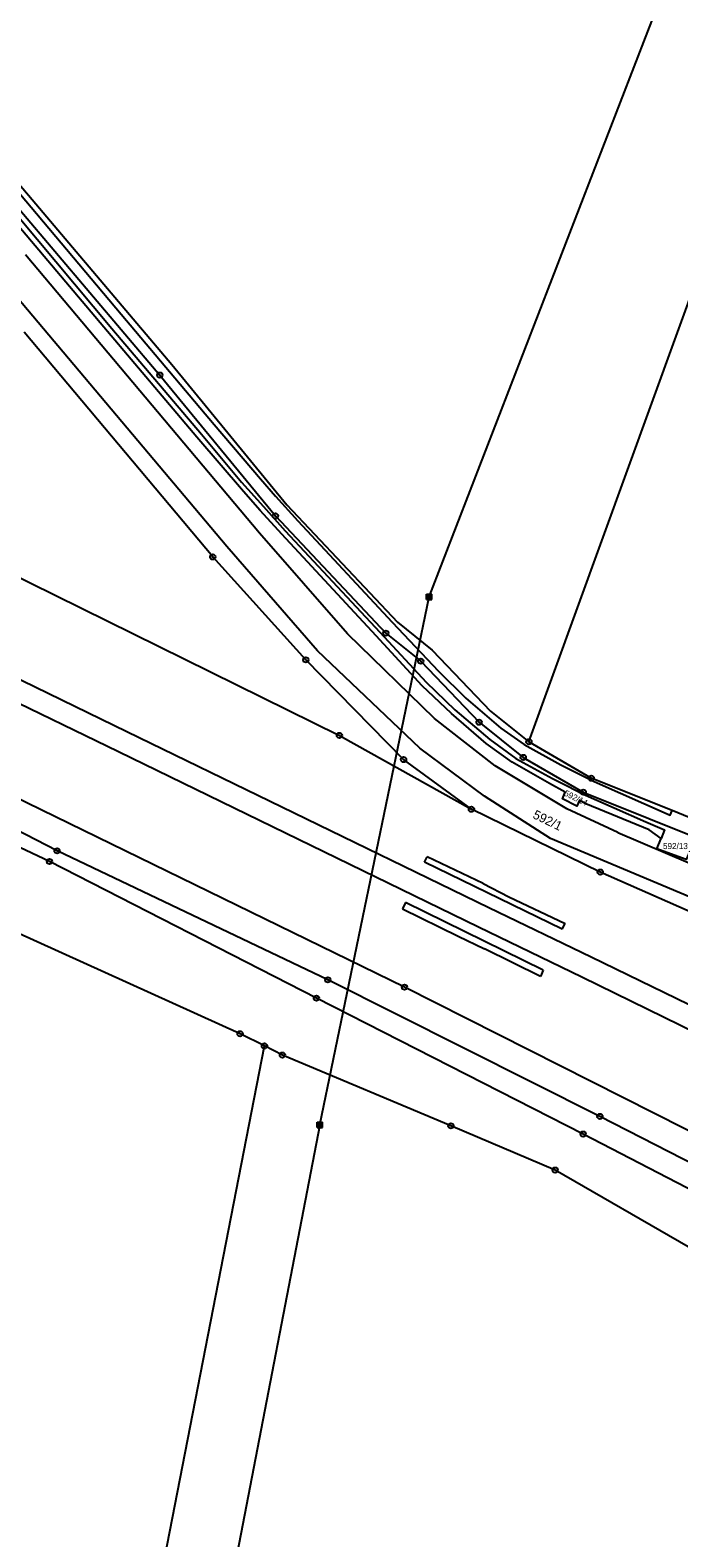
# Model space of a CAD drawing. Extents: x -758582 to -751794, y -998770 to -994350.
# Drawn here: x -754914.8 to -754793.1, y -996434.2 to -996151.5 of the extents above; entities that cross this region are included whole.
import ezdxf

# ---------------------------------------------------------------- set-up
doc = ezdxf.new("R2010")
doc.units = 0
for name, color, linetype in [('Hranice parcel', 7, 'Continuous'), ('Parcelní čísla', 7, 'Continuous'), ('Poz předměty', 7, 'Continuous'), ('Vnitřní kresba', 7, 'Continuous'), ('Značky bodu BP', 7, 'Continuous')]:
    doc.layers.add(name, color=color, linetype=linetype)

msp = doc.modelspace()

# ---------------------------------------------------------------- linework, layer by layer
at = {"layer": 'Hranice parcel'}
msp.add_line((-754791.17, -996299.09), (-754794.37, -996297.81), dxfattribs=at)
for points in [[(-754821.23, -996284.89), (-754765.97, -996132.74), (-754709.63, -995977.66), (-754653.3, -995822.57), (-754611.67, -995707.97)], [(-754662.74, -996423.01), (-754669.27, -996419.49), (-754844.58, -996330.92), (-754994, -996258.05), (-755001.55, -996254.28), (-755006.45, -996251.84), (-755142.05, -996184.14), (-755275.65, -996117.2), (-755276.76, -996116.66)], [(-754665.34, -996427.62), (-754674.53, -996422.22), (-754694.85, -996412.29), (-754729.49, -996394.86), (-754741.54, -996388.96), (-754774.22, -996372.4), (-754807.91, -996355.15), (-754858.97, -996329.54), (-754909.75, -996305.36), (-755002.67, -996257.49), (-755008.53, -996254.77), (-755134.52, -996193.78), (-755139.66, -996190.08), (-755206.85, -996155.12), (-755212.53, -996152.36), (-755248.45, -996133.62), (-755275.54, -996119.52), (-755277.31, -996118.28)], [(-754931.96, -996164.16), (-754914.63, -996184.69), (-754897.71, -996204.74), (-754880.31, -996225.41), (-754871.62, -996235.61), (-754868.79, -996238.83), (-754864.58, -996243.51), (-754846.9, -996262.45), (-754838.23, -996271.69), (-754833.07, -996276.7), (-754826.49, -996282.33), (-754822.11, -996285.41), (-754815.26, -996289.2), (-754809.01, -996292.37), (-754794.73, -996298.64), (-754794.37, -996297.81)], [(-754923.39, -996172.71), (-754921.05, -996175.5), (-754888.21, -996214.18), (-754866.64, -996240.5), (-754845.89, -996262.49), (-754839.36, -996267.74), (-754828.44, -996279.16), (-754821.23, -996284.89)], [(-754923.36, -996177.42), (-754890.48, -996216.15), (-754868.81, -996242.57), (-754848.08, -996264.54), (-754841.54, -996269.8), (-754830.6, -996281.24), (-754822.3, -996287.83), (-754811.04, -996294.35), (-754786.41, -996304.22), (-754720.4, -996335.43), (-754691.23, -996348.26), (-754675.91, -996354.29), (-754642.53, -996363.12), (-754636.09, -996364.43), (-754626.93, -996368.19)], [(-754796.46, -996303.03), (-754798.71, -996301.4), (-754810.57, -996296.55), (-754811.75, -996295.88), (-754812.28, -996297), (-754814.95, -996295.61), (-754814.42, -996294.37), (-754817.36, -996292.71), (-754824.39, -996288.74), (-754829.29, -996285.23), (-754835.79, -996279.61), (-754841.24, -996274.39), (-754849.91, -996265.06), (-754867.58, -996246), (-754871.66, -996241.53), (-754874.8, -996237.98), (-754883.53, -996227.82), (-754900.97, -996207.15), (-754917.93, -996187.09)], [(-754917, -996186.5), (-754899.49, -996207.41), (-754882.68, -996227.22), (-754875.16, -996236.26), (-754871.04, -996240.8), (-754866.94, -996245.34), (-754849.19, -996264.36), (-754840.5, -996273.7), (-754835.12, -996278.91), (-754828.6, -996284.46), (-754823.67, -996288.06), (-754816.79, -996291.78), (-754813.93, -996293.25), (-754811.19, -996294.68), (-754799.28, -996299.93), (-754795.8, -996301.45), (-754796.46, -996303.03)], [(-754667.51, -996431.39), (-754677.38, -996426.56), (-754697.67, -996416.32), (-754732.31, -996398.65), (-754745.35, -996391.09), (-754777.62, -996375.81), (-754811.07, -996358.46), (-754861.11, -996332.99), (-754911.17, -996307.35), (-755005.33, -996262.98), (-755011.09, -996260.31), (-755135.67, -996198.2), (-755141.62, -996197.74)], [(-754870.86, -996341.95), (-754875.42, -996339.64), (-754917.5, -996320.6), (-755010.75, -996273.72), (-755013.69, -996272.26), (-755145.39, -996206.72)], [(-754832.04, -996297.57), (-754844.75, -996288.26), (-754863.09, -996269.54), (-754880.55, -996250.25), (-754915.95, -996208.13)], [(-754986.45, -996219.93), (-754977.82, -996224.07), (-754856.8, -996283.72), (-754832.04, -996297.57)], [(-754794.37, -996297.81), (-754809.54, -996291.75), (-754821.23, -996284.89)], [(-754702.84, -996358.33), (-754751.23, -996334.98), (-754784.15, -996319.77), (-754807.86, -996309.34), (-754832.04, -996297.57)], [(-754791.08, -996305.41), (-754791.76, -996306.99), (-754797.23, -996304.96), (-754796.46, -996303.03)], [(-754938.81, -996690.33), (-754905.88, -996521.51), (-754870.86, -996341.95)], [(-754771.19, -996388.52), (-754791.36, -996379.62), (-754816.32, -996365.21), (-754835.87, -996356.92), (-754867.49, -996343.66), (-754870.86, -996341.95)]]:
    msp.add_lwpolyline(points, dxfattribs=at)
at = {"layer": 'Poz předměty'}
for p, q in [((-754839.98, -996257.7), (-754786.06, -996118.44)), ((-754860.46, -996356.76), (-754839.98, -996257.7)), ((-754840.48, -996257.2), (-754839.48, -996257.2)), ((-754840.48, -996258.2), (-754840.48, -996257.2)), ((-754840.48, -996257.4), (-754839.48, -996257.4)), ((-754840.48, -996257.6), (-754839.48, -996257.6)), ((-754840.48, -996257.8), (-754839.48, -996257.8)), ((-754840.48, -996258), (-754839.48, -996258)), ((-754840.48, -996258.2), (-754839.48, -996258.2)), ((-754840.28, -996258.2), (-754840.28, -996257.2)), ((-754840.08, -996258.2), (-754840.08, -996257.2)), ((-754839.88, -996258.2), (-754839.88, -996257.2)), ((-754839.68, -996258.2), (-754839.68, -996257.2)), ((-754839.48, -996258.2), (-754839.48, -996257.2)), ((-754896.65, -996283.05), (-754930.62, -996266.57)), ((-754898.25, -996286.79), (-754932.39, -996270.22)), ((-754867.56, -996297.18), (-754896.65, -996283.05)), ((-754869.34, -996300.83), (-754898.25, -996286.79)), ((-754828.77, -996316.02), (-754867.56, -996297.18)), ((-754830.67, -996319.65), (-754869.34, -996300.83)), ((-754809.59, -996325.3), (-754828.77, -996316.02)), ((-754811.29, -996329.05), (-754830.67, -996319.65)), ((-754773.87, -996342.63), (-754809.59, -996325.3)), ((-754775.66, -996346.56), (-754811.29, -996329.05)), ((-754860.46, -996356.76), (-754884.38, -996480.69)), ((-754860.96, -996356.26), (-754859.96, -996356.26)), ((-754860.96, -996357.26), (-754860.96, -996356.26)), ((-754860.96, -996356.46), (-754859.96, -996356.46)), ((-754860.96, -996356.66), (-754859.96, -996356.66)), ((-754860.96, -996356.86), (-754859.96, -996356.86)), ((-754860.96, -996357.06), (-754859.96, -996357.06)), ((-754860.76, -996357.26), (-754860.76, -996356.26)), ((-754860.56, -996357.26), (-754860.56, -996356.26)), ((-754860.36, -996357.26), (-754860.36, -996356.26)), ((-754860.16, -996357.26), (-754860.16, -996356.26)), ((-754859.96, -996357.26), (-754859.96, -996356.26)), ((-754860.96, -996357.26), (-754859.96, -996357.26))]:
    msp.add_line(p, q, dxfattribs=at)
at = {"layer": 'Vnitřní kresba'}
for p, q in [((-754871.79, -996245.81), (-754915.69, -996193.6)), ((-754877.91, -996248.32), (-754920.3, -996197.98)), ((-754855.28, -996264.68), (-754871.79, -996245.81)), ((-754860.9, -996267.87), (-754877.91, -996248.32)), ((-754838.98, -996280.53), (-754855.28, -996264.68)), ((-754841.69, -996286.09), (-754860.9, -996267.87)), ((-754827.55, -996289.44), (-754838.98, -996280.53)), ((-754829.58, -996295.12), (-754841.69, -996286.09)), ((-754814.15, -996297.48), (-754827.55, -996289.44)), ((-754817.2, -996303.06), (-754829.58, -996295.12)), ((-754804.59, -996301.93), (-754814.15, -996297.48)), ((-754782.81, -996317.5), (-754817.2, -996303.06)), ((-754804.59, -996301.93), (-754780.59, -996312.15)), ((-754840.83, -996307.47), (-754840.35, -996306.49)), ((-754814.99, -996320.06), (-754840.83, -996307.47)), ((-754829.85, -996311.5), (-754840.35, -996306.49)), ((-754829.85, -996311.5), (-754824.98, -996313.98)), ((-754824.98, -996313.98), (-754814.47, -996318.99)), ((-754844.42, -996315.06), (-754844.98, -996316.21)), ((-754844.98, -996316.21), (-754834.53, -996321.33)), ((-754818.54, -996327.74), (-754844.42, -996315.06)), ((-754814.99, -996320.06), (-754814.47, -996318.99)), ((-754834.53, -996321.33), (-754829.59, -996323.75)), ((-754819.1, -996328.89), (-754829.59, -996323.75)), ((-754818.54, -996327.74), (-754819.1, -996328.89))]:
    msp.add_line(p, q, dxfattribs=at)
at = {"layer": 'Značky bodu BP'}
for centre, radius in [((-754890.48, -996216.15), 0.5), ((-754890.48, -996216.15), 0.0303), ((-754868.81, -996242.57), 0.5), ((-754868.81, -996242.57), 0.0303), ((-754880.55, -996250.25), 0.5), ((-754880.55, -996250.25), 0.0303), ((-754848.08, -996264.54), 0.5), ((-754848.08, -996264.54), 0.0303), ((-754863.09, -996269.54), 0.5), ((-754863.09, -996269.54), 0.0303), ((-754841.54, -996269.8), 0.5), ((-754841.54, -996269.8), 0.0303), ((-754830.6, -996281.24), 0.5), ((-754856.8, -996283.72), 0.5), ((-754830.6, -996281.24), 0.0303), ((-754856.8, -996283.72), 0.0303), ((-754821.23, -996284.89), 0.5), ((-754821.23, -996284.89), 0.0303), ((-754844.75, -996288.26), 0.5), ((-754844.75, -996288.26), 0.0303), ((-754822.3, -996287.83), 0.5), ((-754822.3, -996287.83), 0.0303), ((-754809.54, -996291.75), 0.5), ((-754809.54, -996291.75), 0.0303), ((-754811.04, -996294.35), 0.5), ((-754811.04, -996294.35), 0.0303), ((-754832.04, -996297.57), 0.5), ((-754832.04, -996297.57), 0.0303), ((-754909.75, -996305.36), 0.5), ((-754909.75, -996305.36), 0.0303), ((-754911.17, -996307.35), 0.5), ((-754911.17, -996307.35), 0.0303), ((-754807.86, -996309.34), 0.5), ((-754807.86, -996309.34), 0.0303), ((-754858.97, -996329.54), 0.5), ((-754858.97, -996329.54), 0.0303), ((-754844.58, -996330.92), 0.5), ((-754844.58, -996330.92), 0.0303), ((-754861.11, -996332.99), 0.5), ((-754861.11, -996332.99), 0.0303), ((-754875.42, -996339.64), 0.5), ((-754875.42, -996339.64), 0.0303), ((-754870.86, -996341.95), 0.5), ((-754870.86, -996341.95), 0.0303), ((-754867.49, -996343.66), 0.5), ((-754867.49, -996343.66), 0.0303), ((-754835.87, -996356.92), 0.5), ((-754835.87, -996356.92), 0.0303), ((-754807.91, -996355.15), 0.5), ((-754807.91, -996355.15), 0.0303), ((-754811.07, -996358.46), 0.5), ((-754811.07, -996358.46), 0.0303), ((-754816.32, -996365.21), 0.5), ((-754816.32, -996365.21), 0.0303)]:
    msp.add_circle(centre, radius, dxfattribs=at)

# ---------------------------------------------------------------- texts
at = {"layer": 'Parcelní čísla'}
for s, height, p in [('592/14', 1.139, (-754814.76, -996294.93)), ('592/1', 1.7, (-754820.66, -996299.14))]:
    msp.add_text(s, height=height, rotation=334, dxfattribs=at).set_placement(p)
msp.add_text('592/13', height=1.139, dxfattribs=at).set_placement((-754796.09, -996305.03))

doc.saveas('drawing.dxf')
